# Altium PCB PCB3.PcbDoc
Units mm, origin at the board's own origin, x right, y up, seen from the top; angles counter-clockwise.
Board outline 98.05 x 62.87 mm, 2 copper layers (Top Layer, Bottom Layer); 28 components, 23 nets, 116 pads, 8 vias.
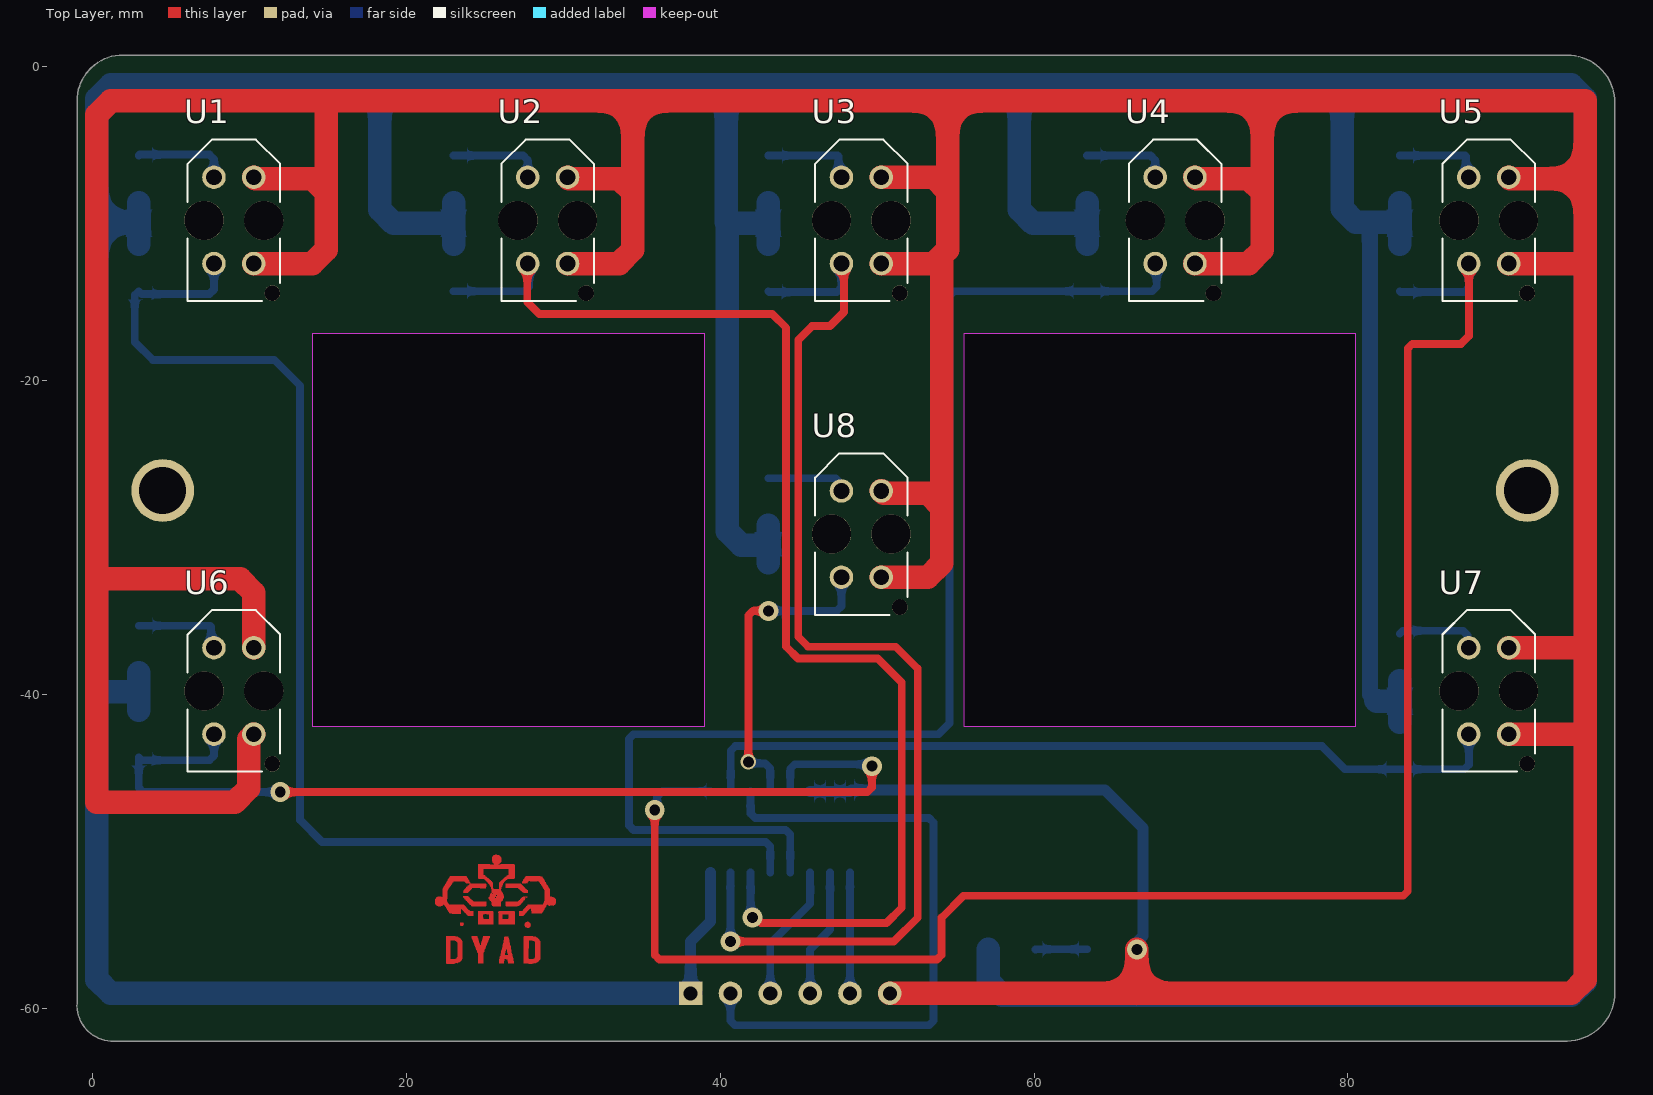
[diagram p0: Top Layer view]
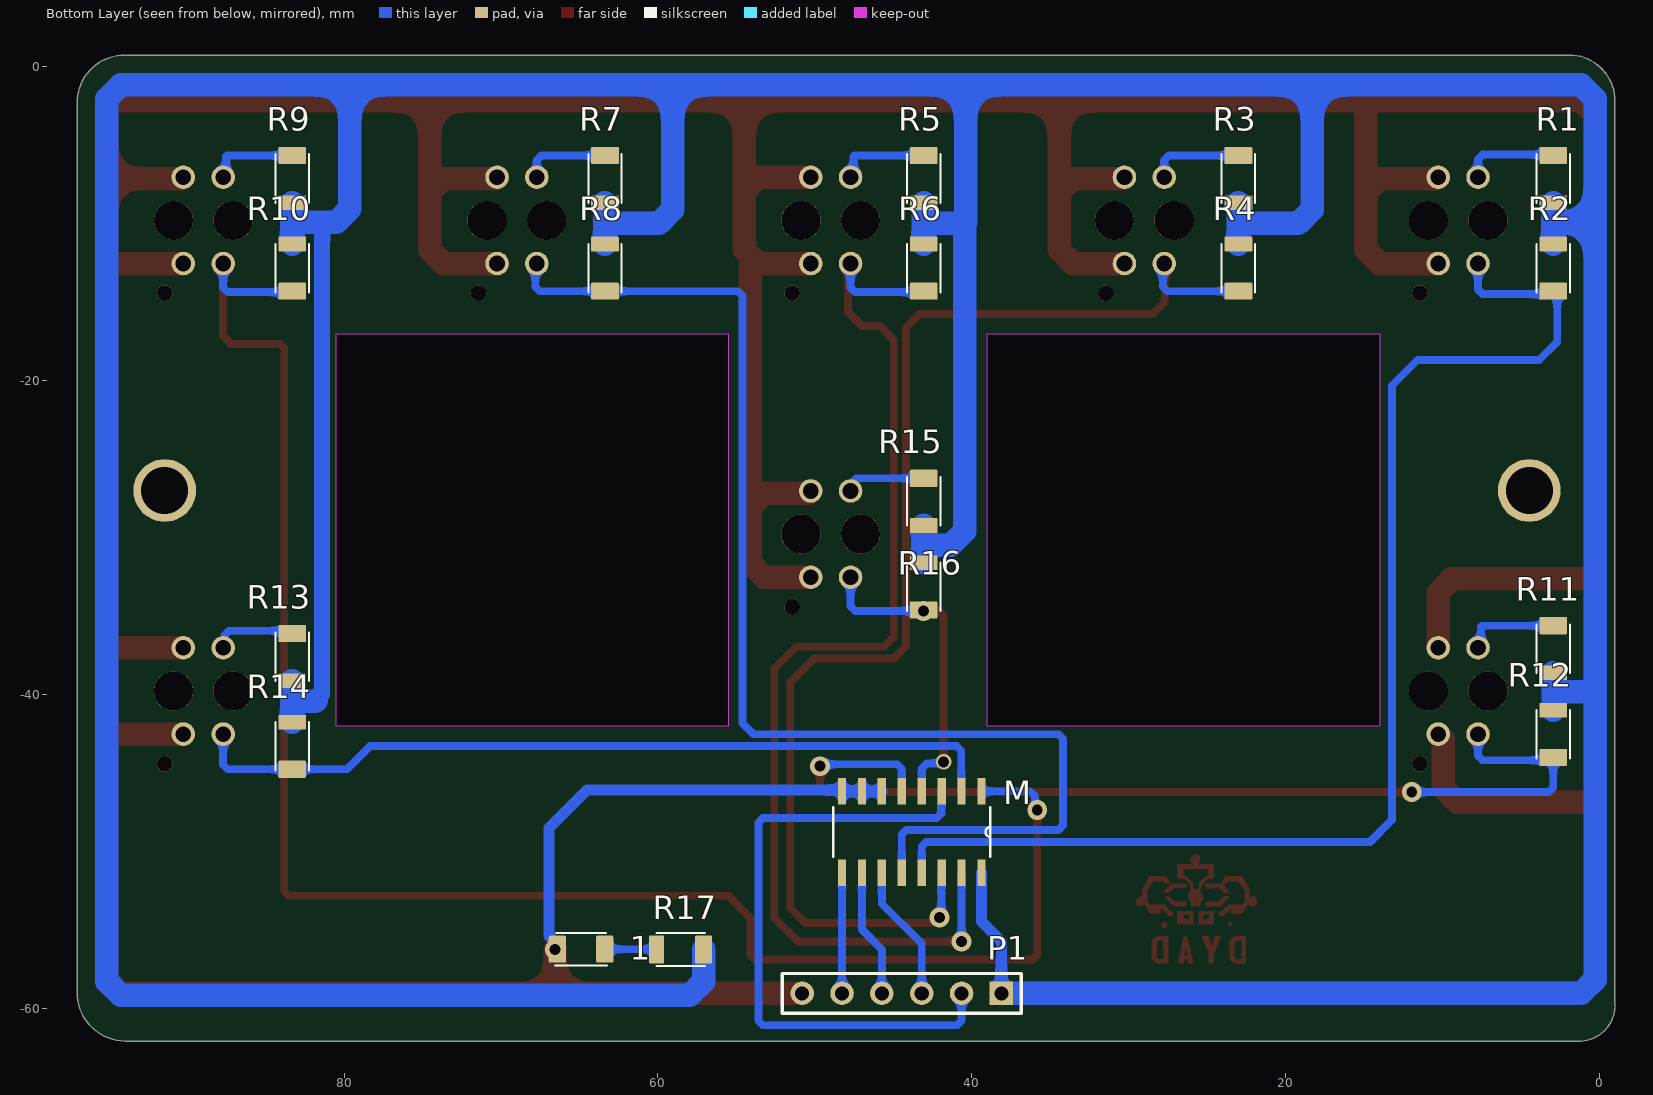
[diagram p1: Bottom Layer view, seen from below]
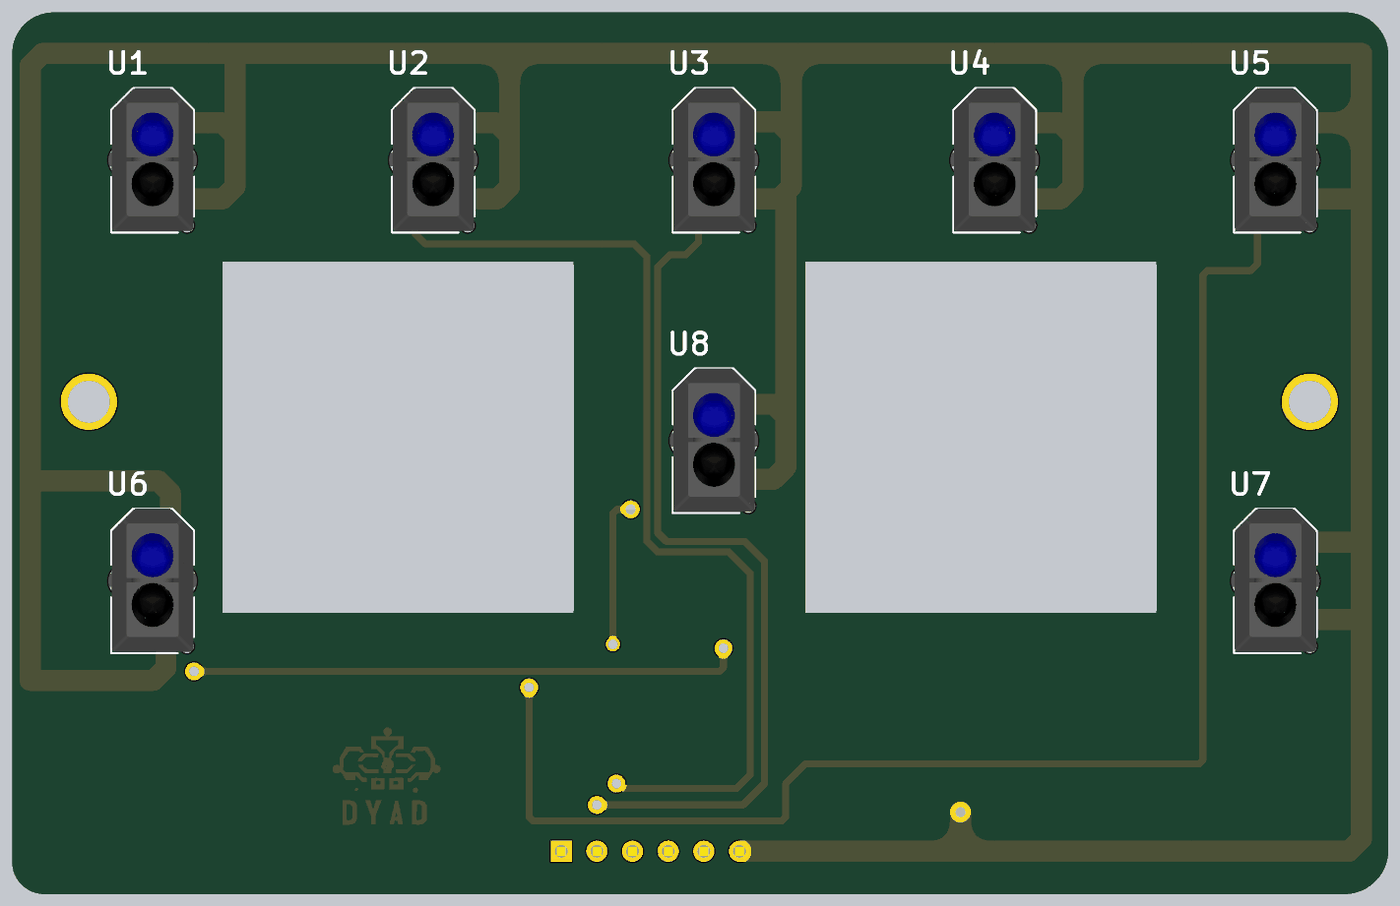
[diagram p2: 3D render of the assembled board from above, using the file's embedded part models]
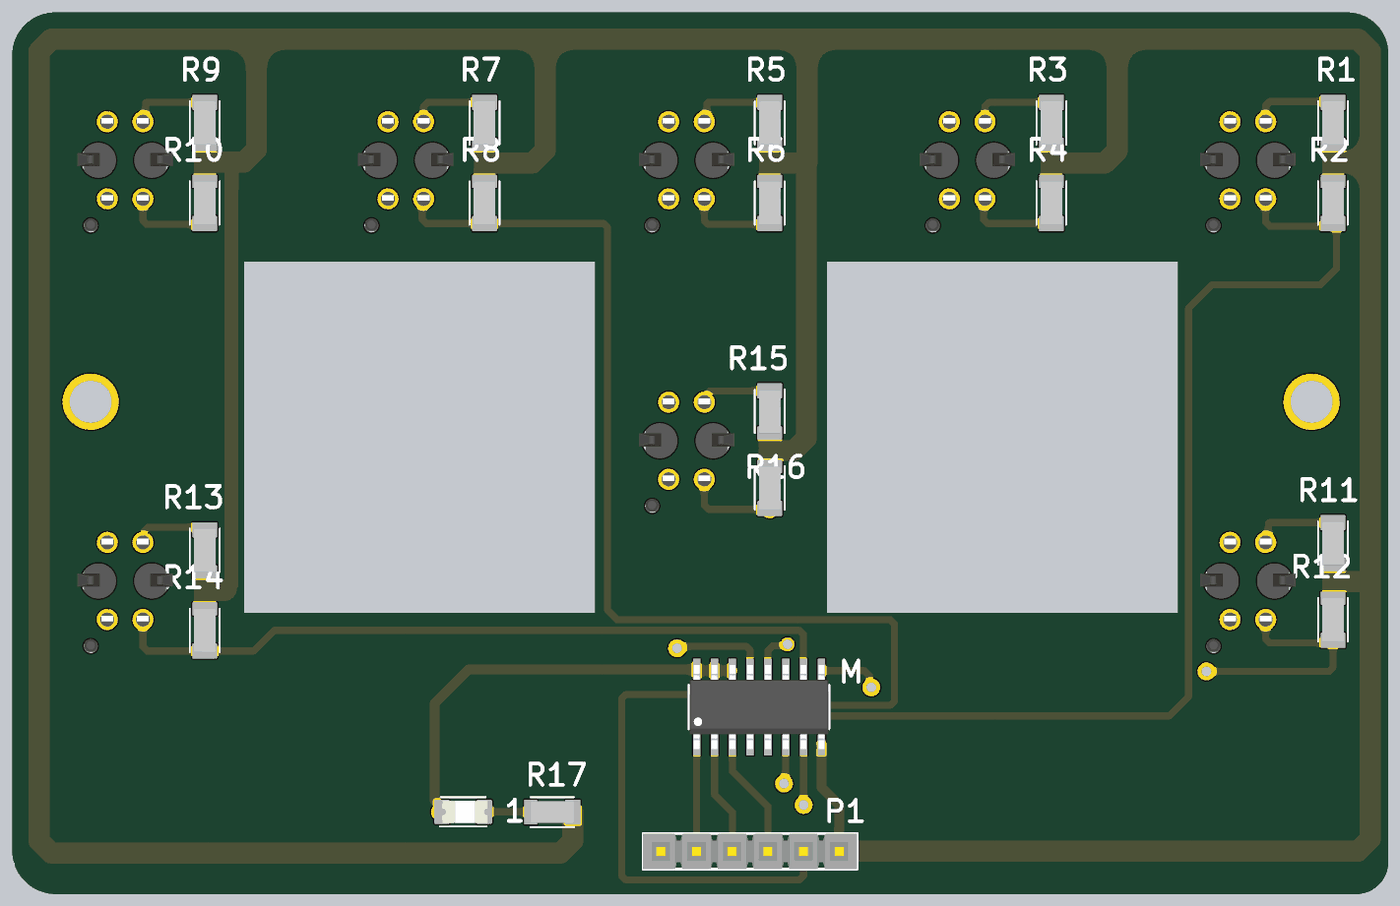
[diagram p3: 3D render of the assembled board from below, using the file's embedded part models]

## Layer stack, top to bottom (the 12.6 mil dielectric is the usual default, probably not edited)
Top Solder: solder mask 0.0102, Solder Resist, Dk 3.5
Top Layer: signal copper 0.0356
Dielectric 1: dielectric 0.32, FR-4, Dk 4.8
Bottom Layer: signal copper 0.0356
Bottom Solder: solder mask 0.0102, Solder Resist, Dk 3.5

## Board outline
1.136,-62.103 cw(c1.27,-59.817) -1.016,-59.686 -1.016,-2.159 cw(c1.905,-2.159) 1.905,0.762 93.98,0.762 cw(c93.98,-2.286) 97.028,-2.286 97.028,-58.928 97.029,-58.991 cw(c93.917,-58.992) 93.983,-62.103 93.98,-62.103
cut-out: 38.989,-42.037 38.989,-17.018 13.97,-17.018 13.97,-42.037
cut-out: 55.499,-42.037 80.518,-42.037 80.518,-17.018 55.499,-17.018

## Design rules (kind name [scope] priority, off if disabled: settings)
Clearance [All] p1: gap=0.254 ignorepadtopadclearanceinfootprint=FALSE except(0: Arc-Hole Track-Hole SMDPad-Hole THPad-Hole Via-Hole Fill-Hole Poly-Hole Region-Hole Text-Hole)
PolygonConnect [All] p1: connectstyle=Relief reliefconductorwidth=0.254 reliefentries=4 polygonreliefangle="90 Angle" airgapwidth=0.254
RoutingVias [All] p1: holewidth=0.711 width=1.27 viastyle="Through Hole" minholewidth=0.711 minwidth=1.27 maxholewidth=0.711 maxwidth=1.27
SolderMaskExpansion [All] p1: expansion=0.102 istentingtop=FALSE
Width [All] p1: maxlimit=2 minlimit=0.5 preferedwidth=1 minimp=50.000000 maximp=50.000000 favimp=50.000000
30 further rules are at their usual default settings.

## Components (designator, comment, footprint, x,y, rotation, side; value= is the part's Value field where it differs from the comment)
1 "LTST-C230KFKT" LEDC3216X110 64.897,-56.241 r180 bottom
M "74HC4051D" SOIC127P600X175-16N 43.815,-48.768 r270 bottom
P1 "Header 6" HDR1X6 38.1,-59.055 r0 bottom
R1 "220" RESC3115X65N 2.921,-7.112 r270 bottom
R2 "2K" RESC3115X65N 2.921,-12.827 r90 bottom
R3 "220" RESC3115X65N 22.987,-7.112 r270 bottom
R4 "2K" RESC3115X65N 22.987,-12.827 r90 bottom
R5 "220" RESC3115X65N 43.053,-7.112 r270 bottom
R6 "2K" RESC3115X65N 43.053,-12.827 r90 bottom
R7 "220" RESC3115X65N 63.373,-7.112 r270 bottom
R8 "2K" RESC3115X65N 63.373,-12.827 r90 bottom
R9 "220" RESC3115X65N 83.312,-7.112 r270 bottom
R10 "2K" RESC3115X65N 83.312,-12.827 r90 bottom
R11 "220" RESC3115X65N 2.921,-37.084 r270 bottom
R12 "2K" RESC3115X65N 2.921,-42.545 r90 bottom
R13 "220" RESC3115X65N 83.312,-37.592 r270 bottom
R14 "2K" RESC3115X65N 83.312,-43.307 r90 bottom
R15 "220" RESC3115X65N 43.053,-27.686 r270 bottom
R16 "2K" RESC3115X65N 43.053,-33.147 r90 bottom
R17 "1879462-3" RESC3115X65N 58.547,-56.261 r0 bottom
U1 "IR_SENSOR" OPTO_TCRT5000 8.984,-9.779 r90 top
U2 "IR_SENSOR" OPTO_TCRT5000 28.984,-9.779 r90 top
U3 "IR_SENSOR" OPTO_TCRT5000 48.984,-9.779 r90 top
U4 "IR_SENSOR" OPTO_TCRT5000 68.984,-9.779 r90 top
U5 "IR_SENSOR" OPTO_TCRT5000 88.984,-9.779 r90 top
U6 "IR_SENSOR" OPTO_TCRT5000 8.984,-39.779 r90 top
U7 "IR_SENSOR" OPTO_TCRT5000 88.984,-39.779 r90 top
U8 "IR_SENSOR" OPTO_TCRT5000 48.984,-29.779 r90 top

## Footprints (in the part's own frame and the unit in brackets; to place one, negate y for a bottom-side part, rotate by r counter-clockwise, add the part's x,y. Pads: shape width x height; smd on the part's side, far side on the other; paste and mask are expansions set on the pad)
HDR1X6 [mm] "Connector; Header; 6 Position"
  rect 1.5x1.5 hole 0.9: 1(0,0)
  round 1.5 hole 0.9: 2(2.54,0) 3(5.08,0) 4(7.62,0) 5(10.16,0) 6(12.7,0)
  silkscreen extent -1.27,-1.27 13.97,1.27, body extent -1.26,-1.25 13.98,1.29, height 8.38
LEDC3216X110 [mm]
  rrect20% 1.1x1.73 smd: A(1.51,0) C(-1.51,0)
  silkscreen extent -1.65,-1.04 1.65,1.04, body extent -1.47,-0.8 1.73,0.8, height 1.13
OPTO_TCRT5000 [mm]
  round 1.5 hole 1: A(2.75,1.27) CATH(2.75,-1.27) COLL(-2.75,1.27) E(-2.75,-1.27)
  round 1 hole 1 unplated: ""(-4.65,-2.45)
  round 2.5 hole 2.5 unplated: ""(0,1.9) ""(0,-1.9)
  silkscreen extent -5.15,-2.95 5.15,2.95, body extent -5.04,-3.4 5.16,3.4, height 7.2
RESC3115X65N [mm]
  rrect14% 1.09x1.77 smd: 1(-1.465,0)
  rrect14% 0.94x1.77 smd: 2(1.54,0)
  silkscreen extent -1.55,-1.06 1.55,1.06, body extent -1.55,-0.77 1.55,0.77, height 0.53
SOIC127P600X175-16N [mil]
  rect 67x21 smd: 1(-102,175) 2(-102,125) 3(-102,75) 4(-102,25) 5(-102,-25) 6(-102,-75) 7(-102,-125) 8(-102,-175) 9(102,-175) 10(102,-125) 11(102,-75) 12(102,-25) 13(102,25) 14(102,75) 15(102,125) 16(102,175)
  silkscreen extent -62,-197 62,197, body extent -118,-195 118,195, height 67

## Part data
1: "Orange 605nm LED Indication - Discrete 2V 1206 (3216 Metric)", Package="1206 Lite-On"
M: "1 Circuit IC Switch 8:1 130Ohm 16-SOIC", Package="SOIC-16 Toshiba"
P1: "Header, 6-Pin"
R1 R2 R3 R4 R5 R6 R7 R8 R9 R10 R11 R12 R13 R14 R15 R16: library part 1879462-3, "RL73H 2B R12 1% 5K RL", Package=None
R17: "RL73H 2B R12 1% 5K RL", Package=None
U1 U2 U3 U4 U5 U6 U7 U8: library part TCRT5000, "950 nm 60 mA Through Hole Reflective Optical Sensor with Transistor Output", Package=None

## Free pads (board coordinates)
  round 4 hole 3: 6(4.445,-27) 6(91.44,-27)

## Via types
v1: diameter 1.27, hole 0.7, Top Layer to Bottom Layer, 7 vias
v2: diameter 1, hole 0.7, Top Layer to Bottom Layer, 1 vias

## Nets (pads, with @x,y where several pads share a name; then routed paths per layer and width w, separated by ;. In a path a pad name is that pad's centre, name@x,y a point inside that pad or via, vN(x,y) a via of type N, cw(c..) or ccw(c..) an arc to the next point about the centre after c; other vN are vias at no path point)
+5: M.16 P1.1 R1.2 R2.2 R3.2 R4.2 R5.2 R6.2 R7.2 R8.2 R9.2 R10.2 R11.2 R12.2 R13.2 R14.2 R15.2 R16.2 R17.1 | length 424.9
  Bottom Layer w0.7: P1.1 38.1,-55.753 39.37,-54.483 M.16
  Bottom Layer w1: 81.407,-9.906 81.407,-40.005 81.788,-40.386
  Bottom Layer w1.5: R12.2 2.921,-39.814 ; R11.2 2.921,-39.814 ; R2.2 2.921,-9.97 ; R1.2 2.921,-9.97 ; R4.2 22.987,-9.97 ; R3.2 22.987,-9.97 ; P1.1 1.133,-59.055 0.254,-58.176 0.254,-39.878 ; 42.873,-30.48 41.328,-30.48 40.45,-29.601 40.45,-9.97 ; R16.2 R15.2 ; R6.2 43.053,-9.97 ; R5.2 43.053,-9.97 ; R17.1 57.082,-58.303 57.961,-59.182 94.244,-59.182 95.123,-58.303 95.123,-2.022 94.244,-1.143 79.629,-1.143 ; R8.2 63.373,-9.97 ; R7.2 63.373,-9.97 ; 81.788,-40.386 81.852,-40.45 83.312,-40.45 ; R14.2 83.312,-40.45 ; R13.2 83.312,-40.45 ; R10.2 83.312,-9.97 ; R9.2 83.312,-9.97 ; 0.254,-39.878 0.254,-9.906 ; 0.254,-39.878 0.318,-39.814 2.921,-39.814 ; 0.254,-9.906 0.254,-2.022 1.133,-1.143 18.288,-1.143 ; 0.254,-9.906 2.857,-9.906 2.921,-9.97 ; 18.288,-1.143 40.386,-1.143 ; 18.288,-1.143 18.288,-9.091 19.167,-9.97 22.987,-9.97 ; 40.386,-1.143 40.386,-9.906 40.45,-9.97 ; 40.386,-1.143 59.055,-1.143 ; 40.45,-9.97 43.053,-9.97 ; 59.055,-1.143 79.629,-1.143 ; 59.055,-1.143 59.055,-9.091 59.934,-9.97 63.373,-9.97 ; 79.629,-1.143 79.629,-9.027 80.508,-9.906 81.407,-9.906 83.248,-9.906 83.312,-9.97
A1: M.3 P1.2 | length 40.9
  Bottom Layer w0.5: P1.2 40.64,-60.794 40.933,-61.087 53.301,-61.087 53.594,-60.794 53.594,-48.172 53.301,-47.879 42.22,-47.879 41.927,-47.586 41.927,-46.194 M.3
D1: M.11 P1.3 | length 8.7
  Bottom Layer w0.5: P1.3 43.18,-55.88 45.72,-53.34 M.11
D2: M.10 P1.4 | length 8.2
  Bottom Layer w0.5: P1.4 45.72,-56.261 46.99,-54.991 M.10
D3: M.9 P1.5 | length 7.7
  Bottom Layer w0.5: P1.5 M.9
GND: 1.C M.6 M.7 M.8 P1.6 U1.CATH U1.E U2.CATH U2.E U3.CATH U3.E U4.CATH U4.E U5.CATH U5.E U6.CATH U6.E U7.CATH U7.E U8.CATH U8.E | length 423.8
  Top Layer w1.5: U6.E 9.93,-42.853 9.93,-45.984 9.051,-46.863 0.254,-46.863 0.254,-32.512 ; U6.CATH 10.254,-33.518 9.375,-32.639 0.381,-32.639 0.254,-32.512 ; U1.E 13.98,-12.529 14.859,-11.65 14.859,-7.991 ; U1.CATH 10.337,-7.112 13.98,-7.112 14.859,-7.991 ; U2.E 33.538,-12.529 34.417,-11.65 34.417,-7.991 ; U2.CATH 30.337,-7.112 33.538,-7.112 34.417,-7.991 ; U8.E 53.223,-32.529 54.102,-31.65 54.102,-28.057 ; U8.CATH 50.403,-27.178 53.223,-27.178 54.102,-28.057 ; U3.E 53.604,-12.529 54.483,-11.65 54.483,-7.908 ; U3.CATH 53.604,-7.029 54.483,-7.908 ; P1.6 66.548,-59.055 ; 54.102,-12.031 54.102,-28.057 ; v1(66.548,-56.261) 66.548,-59.055 ; U4.E 73.67,-12.529 74.549,-11.65 74.549,-7.991 ; U4.CATH 70.337,-7.112 73.67,-7.112 74.549,-7.991 ; U7.E 94.98,-42.529 95.123,-42.672 ; U7.CATH 95.068,-37.029 95.123,-37.084 ; U5.E 95.079,-12.529 95.123,-12.573 ; U5.CATH 90.337,-7.112 95.123,-7.112 ; 0.254,-32.512 0.254,-3.038 1.133,-2.159 14.605,-2.159 ; 14.605,-2.159 34.417,-2.159 ; 14.605,-2.159 14.859,-2.413 14.859,-7.991 ; 34.417,-7.991 34.417,-2.159 ; 34.417,-2.159 54.483,-2.159 ; 54.483,-7.908 54.483,-2.159 ; 54.483,-2.159 74.549,-2.159 ; 66.548,-59.055 94.244,-59.055 95.123,-58.176 95.123,-42.672 ; 74.549,-7.991 74.549,-2.159 ; 74.549,-2.159 95.123,-2.159 95.123,-7.112 ; 95.123,-42.672 95.123,-37.084 ; 95.123,-37.084 95.123,-12.573 ; 95.123,-12.573 95.123,-7.112
  Bottom Layer w0.7: M.6 M.7 M.8 48.343,-46.094 64.509,-46.094 66.929,-48.514 66.929,-55.404 66.548,-55.785 v1(66.548,-56.261) 1.C@66.421,-56.134
Net1_A: 1.A R17.2 | length 3.3
  Bottom Layer w0.5: R17.2 60.107,-56.241 1.A
NetR1_1: R1.1 U1.A | length 6.1
  Bottom Layer w0.5: R1.1 2.98,-5.588 7.421,-5.588 7.714,-5.881 U1.A
NetR3_1: R3.1 U2.A | length 5.9
  Bottom Layer w0.5: R3.1 27.421,-5.647 27.714,-5.94 U2.A
NetR5_1: R5.1 U3.A | length 5.9
  Bottom Layer w0.5: R5.1 47.459,-5.647 47.523,-5.711 47.523,-6.838 U3.A
NetR7_1: R7.1 U4.A | length 5.6
  Bottom Layer w0.5: R7.1 67.421,-5.647 67.714,-5.94 U4.A
NetR9_1: R9.1 U5.A | length 5.6
  Bottom Layer w0.5: R9.1 87.464,-5.647 87.523,-5.706 87.523,-6.838 U5.A
NetR11_1: R11.1 U6.A | length 6.1
  Bottom Layer w0.5: R11.1 7.454,-35.619 7.523,-35.688 7.523,-36.838 U6.A
NetR13_1: R13.1 U7.A | length 5.3
  Bottom Layer w0.5: R13.1 83.498,-35.941 87.337,-35.941 87.63,-36.234 87.63,-36.945 U7.A
NetR15_1: R15.1 U8.A | length 5.2
  Bottom Layer w0.5: R15.1 47.332,-26.221 47.625,-26.514 47.625,-26.94 U8.A
S1: M.13 R2.1 U1.COLL | length 81.7
  Bottom Layer w0.5: U1.COLL 7.714,-14.185 7.421,-14.478 3.107,-14.478 R2.1 2.667,-14.546 2.667,-17.526 3.81,-18.669 11.557,-18.669 13.208,-20.32 13.208,-48.006 14.605,-49.403 42.887,-49.403 43.18,-49.696 M.13
S2: M.14 R4.1 U2.COLL | length 82.1
  Top Layer w0.5: U2.COLL 27.686,-12.557 27.686,-14.986 28.448,-15.748 43.307,-15.748 44.192,-16.633 44.192,-36.953 44.95,-37.711 50.03,-37.711 51.562,-39.243 51.562,-53.594 50.59,-54.566 42.583,-54.566 42.245,-54.229 v1(42.037,-54.229)
  Bottom Layer w0.5: R4.1 27.52,-14.292 27.813,-13.999 27.813,-12.628 U2.COLL ; M.14 41.927,-51.376 41.927,-54.119 v1(42.037,-54.229)
S3: M.15 R6.1 U3.COLL | length 73.4
  Top Layer w0.5: v1(40.64,-55.753) 51.054,-55.753 52.578,-54.229 52.578,-38.354 51.181,-36.957 45.593,-36.957 44.958,-36.322 44.958,-17.399 45.847,-16.51 46.99,-16.51 47.879,-15.621 47.879,-12.694 U3.COLL
  Bottom Layer w0.5: v1(40.64,-55.753) M.15 ; R6.1 43.112,-14.351 47.421,-14.351 47.714,-14.058 U3.COLL
S4: M.12 R8.1 U4.COLL | length 81.5
  Bottom Layer w0.5: M.12 44.45,-48.934 44.157,-48.641 34.464,-48.641 34.171,-48.348 34.171,-42.834 34.464,-42.541 53.909,-42.541 54.61,-41.84 54.61,-14.585 54.903,-14.292 R8.1 67.525,-14.292 67.818,-13.999 67.818,-12.633 U4.COLL
S5: M.1 R10.1 U5.COLL | length 114.5
  Top Layer w0.5: v1(35.814,-47.367) 35.814,-56.603 36.107,-56.896 53.809,-56.896 54.102,-56.603 54.102,-54.229 55.499,-52.832 83.527,-52.832 83.82,-52.539 83.82,-17.946 84.113,-17.653 87.21,-17.653 87.714,-17.149 U5.COLL
  Bottom Layer w0.5: v1(35.814,-47.367) 35.961,-47.22 35.961,-46.508 36.292,-46.177 M.1 ; R10.1 83.371,-14.351 87.421,-14.351 87.714,-14.058 U5.COLL
S6: M.5 R12.1 U6.COLL | length 63.4
  Top Layer w0.5: v1(11.938,-46.228) 49.364,-46.228 49.657,-45.935 v1(49.657,-44.577)
  Bottom Layer w0.5: U6.COLL 7.714,-43.903 7.421,-44.196 3.107,-44.196 R12.1 2.921,-45.935 3.214,-46.228 v1(11.938,-46.228) ; M.5 44.45,-44.743 44.743,-44.45 49.53,-44.45 v1(49.657,-44.577)
S7: M.2 R14.1 U7.COLL | length 52.5
  Bottom Layer w0.5: M.2 40.657,-46.16 40.657,-43.588 40.95,-43.295 78.347,-43.295 79.824,-44.772 R14.1 87.421,-44.772 87.714,-44.479 U7.COLL
S8: M.4 R16.1 U8.COLL | length 20.4
  Top Layer w0.5: v2(41.783,-44.299) 41.783,-34.964 42.076,-34.671 v1(43.053,-34.671)
  Bottom Layer w0.5: v2(41.783,-44.299) 41.879,-44.395 42.848,-44.395 43.18,-44.727 M.4 ; v1(43.053,-34.671) 47.421,-34.671 47.714,-34.378 U8.COLL
pads on no net: U1. U2. U3. U4. U5. U6. U7. U8.

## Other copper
Top Layer:
  region: 25.303,-52.703 25.322,-52.703 25.322,-52.723 25.303,-52.723
  region: 25.342,-52.703 25.361,-52.703 25.361,-52.742 25.342,-52.742 25.342,-52.723
  region: 23.091,-55.439 23.188,-55.439 23.188,-55.458 23.246,-55.458 23.246,-55.478 23.285,-55.478 23.285,-55.497 23.324,-55.497 23.324,-55.517 23.343,-55.517 23.343,-55.536 23.363,-55.536 23.363,-55.555 23.402,-55.555 23.402,-55.575 23.421,-55.575 23.421,-55.594 23.44,-55.594 23.44,-55.614 23.46,-55.614 23.46,-55.652 23.479,-55.652 23.479,-55.672 23.499,-55.672 23.499,-55.711 23.518,-55.711 23.518,-55.749 23.537,-55.749 23.537,-55.788 23.557,-55.788 23.557,-56.797 23.537,-56.797 23.537,-56.836 23.518,-56.836 23.518,-56.894 23.499,-56.894 23.499,-56.933 23.479,-56.933 23.479,-56.952 23.46,-56.952 23.46,-56.972 23.44,-56.972 23.44,-56.991 23.421,-56.991 23.421,-57.011 23.402,-57.011 23.402,-57.03 23.382,-57.03 23.382,-57.049 23.343,-57.049 23.343,-57.069 23.304,-57.069 23.304,-57.088 23.266,-57.088 23.266,-57.108 23.207,-57.108 23.207,-57.127 23.11,-57.127 23.11,-57.146 23.033,-57.146 23.033,-57.166 22.548,-57.166 22.548,-57.146 22.509,-57.146 22.509,-55.42 23.091,-55.42 hole: 23.052,-55.711 22.819,-55.711 22.819,-56.836 22.839,-56.836 22.839,-56.855 23.013,-56.855 23.013,-56.836 23.11,-56.836 23.11,-56.817 23.149,-56.817 23.149,-56.797 23.169,-56.797 23.169,-56.758 23.188,-56.758 23.188,-56.72 23.207,-56.72 23.207,-55.846 23.188,-55.846 23.188,-55.808 23.169,-55.808 23.169,-55.769 23.13,-55.769 23.13,-55.749 23.11,-55.749 23.11,-55.73 23.052,-55.73
  region: 23.421,-54.702 23.402,-54.702 23.402,-54.605 23.421,-54.605 23.421,-54.566 23.44,-54.566 23.44,-54.546 23.576,-54.546 23.576,-54.566 23.615,-54.566 23.615,-54.624 23.634,-54.624 23.634,-54.644 23.615,-54.644 23.615,-54.702 23.596,-54.702 23.596,-54.721 23.576,-54.721 23.576,-54.741 23.557,-54.741 23.557,-54.76 23.479,-54.76 23.479,-54.741 23.44,-54.741 23.44,-54.721 23.421,-54.721
  region: 27.787,-54.857 27.767,-54.857 27.767,-54.876 27.67,-54.876 27.67,-54.857 27.612,-54.857 27.612,-54.838 27.593,-54.838 27.593,-54.818 27.573,-54.818 27.573,-54.799 27.554,-54.799 27.554,-54.741 27.534,-54.741 27.534,-54.605 27.554,-54.605 27.554,-54.566 27.573,-54.566 27.573,-54.546 27.612,-54.546 27.612,-54.527 27.67,-54.527 27.67,-54.508 27.748,-54.508 27.748,-54.527 27.787,-54.527 27.787,-54.546 27.845,-54.546 27.845,-54.585 27.864,-54.585 27.864,-54.605 27.884,-54.605 27.884,-54.682 27.903,-54.682 27.903,-54.721 27.884,-54.721 27.884,-54.799 27.864,-54.799 27.864,-54.818 27.845,-54.818 27.845,-54.838 27.825,-54.838 27.825,-54.857 27.806,-54.857
  region: 26.758,-53.829 26.855,-53.829 26.855,-53.848 26.875,-53.848 26.875,-54.644 25.866,-54.644 25.866,-54.139 25.866,-54.12 25.866,-53.906 25.846,-53.906 25.846,-53.887 25.866,-53.887 25.866,-53.829 26.215,-53.829 26.215,-53.809 26.758,-53.809 hole: 26.448,-54.042 26.118,-54.042 26.118,-54.275 26.137,-54.275 26.137,-54.294 26.448,-54.294 26.448,-54.275 26.487,-54.275 26.487,-54.12 26.467,-54.12 26.467,-54.061 26.448,-54.061
  region: 24.779,-53.499 24.139,-53.499 24.139,-53.479 24.119,-53.479 24.119,-53.441 24.1,-53.441 24.1,-53.421 24.081,-53.421 24.081,-53.402 24.061,-53.402 24.061,-53.382 24.042,-53.382 24.042,-53.363 24.003,-53.363 24.003,-53.324 23.984,-53.324 23.984,-53.305 23.964,-53.305 23.964,-53.285 23.945,-53.285 23.945,-53.266 23.925,-53.266 23.925,-53.247 23.906,-53.247 23.906,-53.227 23.887,-53.227 23.887,-53.208 23.867,-53.208 23.867,-53.188 23.848,-53.188 23.848,-53.169 23.828,-53.169 23.828,-53.149 23.809,-53.149 23.809,-53.13 23.79,-53.13 23.79,-53.111 23.77,-53.111 23.77,-53.091 23.751,-53.091 23.751,-53.052 23.712,-53.052 23.712,-53.014 23.693,-53.014 23.693,-52.994 23.673,-52.994 23.673,-52.975 23.654,-52.975 23.654,-52.955 23.634,-52.955 23.634,-52.917 23.615,-52.917 23.615,-52.878 23.906,-52.878 23.906,-52.897 23.945,-52.897 23.945,-52.936 23.984,-52.936 23.984,-52.955 24.003,-52.955 24.003,-52.994 24.022,-52.994 24.022,-53.014 24.042,-53.014 24.042,-53.033 24.061,-53.033 24.061,-53.052 24.081,-53.052 24.081,-53.072 24.1,-53.072 24.1,-53.091 24.119,-53.091 24.119,-53.111 24.158,-53.111 24.158,-53.13 24.178,-53.13 24.178,-53.149 24.197,-53.149 24.197,-53.169 24.216,-53.169 24.216,-53.188 24.236,-53.188 24.236,-53.208 25.051,-53.208 25.051,-53.227 25.07,-53.227 25.07,-53.479 25.051,-53.479 25.051,-53.499 24.799,-53.499
  region: 27.185,-52.082 27.282,-52.082 27.282,-52.102 27.301,-52.102 27.301,-52.121 27.321,-52.121 27.321,-52.141 27.34,-52.141 27.34,-52.16 27.36,-52.16 27.36,-52.179 27.379,-52.179 27.379,-52.199 27.398,-52.199 27.398,-52.218 27.418,-52.218 27.418,-52.238 27.437,-52.238 27.437,-52.276 27.476,-52.276 27.476,-52.296 27.495,-52.296 27.495,-52.315 27.515,-52.315 27.515,-52.335 27.534,-52.335 27.534,-52.354 27.554,-52.354 27.554,-52.373 27.573,-52.373 27.573,-52.412 27.612,-52.412 27.612,-52.432 27.631,-52.432 27.631,-52.451 27.651,-52.451 27.651,-52.47 27.67,-52.47 27.67,-52.49 27.709,-52.49 27.709,-52.509 27.728,-52.509 27.728,-52.626 27.709,-52.626 27.709,-52.645 27.476,-52.645 27.476,-52.626 27.437,-52.626 27.437,-52.606 27.398,-52.606 27.398,-52.587 27.379,-52.587 27.379,-52.567 27.36,-52.567 27.36,-52.548 27.34,-52.548 27.34,-52.529 27.321,-52.529 27.321,-52.509 27.301,-52.509 27.301,-52.49 27.282,-52.49 27.282,-52.47 27.243,-52.47 27.243,-52.451 27.224,-52.451 27.224,-52.432 27.204,-52.432 27.204,-52.412 27.185,-52.412 27.185,-52.393 27.166,-52.393 27.166,-52.373 27.146,-52.373 27.146,-52.354 27.127,-52.354 27.127,-52.335 26.312,-52.335 26.312,-52.082 27.166,-52.082
  region: 24.934,-53.829 25.478,-53.829 25.478,-53.848 25.516,-53.848 25.516,-54.023 25.516,-54.042 25.516,-54.644 24.566,-54.644 24.566,-53.829 24.837,-53.829 24.837,-53.809 24.857,-53.809 24.857,-53.829 24.896,-53.829 24.896,-53.809 24.934,-53.809 hole: 25.07,-54.023 24.973,-54.023 24.973,-54.042 24.915,-54.042 24.915,-54.061 24.896,-54.061 24.896,-54.217 24.915,-54.217 24.915,-54.294 25.225,-54.294 25.225,-54.042 25.07,-54.042
  region: 26.467,-55.458 26.487,-55.458 26.487,-55.555 26.506,-55.555 26.506,-55.652 26.525,-55.652 26.525,-55.749 26.545,-55.749 26.545,-55.846 26.564,-55.846 26.564,-55.924 26.584,-55.924 26.584,-55.982 26.603,-55.982 26.603,-56.041 26.603,-56.06 26.622,-56.06 26.622,-56.176 26.642,-56.176 26.642,-56.293 26.661,-56.293 26.661,-56.39 26.681,-56.39 26.681,-56.487 26.7,-56.487 26.7,-56.564 26.719,-56.564 26.719,-56.623 26.739,-56.623 26.739,-56.72 26.758,-56.72 26.758,-56.817 26.778,-56.817 26.778,-56.914 26.797,-56.914 26.797,-57.011 26.816,-57.011 26.816,-57.146 26.506,-57.146 26.506,-57.127 26.487,-57.127 26.487,-57.049 26.467,-57.049 26.467,-57.011 26.448,-57.011 26.448,-56.894 26.428,-56.894 26.428,-56.875 26.351,-56.875 26.351,-56.855 26.234,-56.855 26.234,-56.875 26.215,-56.875 26.215,-56.972 26.196,-56.972 26.196,-57.069 26.176,-57.069 26.176,-57.127 26.157,-57.127 26.157,-57.146 25.904,-57.146 25.904,-57.127 25.885,-57.127 25.885,-56.991 25.904,-56.991 25.904,-56.894 25.924,-56.894 25.924,-56.817 25.943,-56.817 25.943,-56.739 25.963,-56.739 25.963,-56.7 25.982,-56.7 25.982,-56.623 26.001,-56.623 26.001,-56.526 26.021,-56.526 26.021,-56.429 26.04,-56.429 26.04,-56.351 26.06,-56.351 26.06,-56.273 26.079,-56.273 26.079,-56.215 26.098,-56.215 26.098,-56.138 26.118,-56.138 26.118,-56.041 26.137,-56.041 26.137,-55.963 26.157,-55.963 26.157,-55.866 26.176,-55.866 26.176,-55.769 26.196,-55.769 26.196,-55.672 26.215,-55.672 26.215,-55.614 26.234,-55.614 26.234,-55.478 26.254,-55.478 26.254,-55.439 26.467,-55.439 hole: 26.37,-56.293 26.351,-56.293 26.351,-56.332 26.331,-56.332 26.331,-56.37 26.312,-56.37 26.312,-56.429 26.312,-56.448 26.312,-56.506 26.293,-56.506 26.293,-56.603 26.37,-56.603 26.37,-56.584 26.428,-56.584 26.428,-56.564 26.409,-56.564 26.409,-56.467 26.39,-56.467 26.39,-56.39 26.37,-56.39
  region: 27.67,-52.917 27.651,-52.917 27.651,-52.936 27.631,-52.936 27.631,-52.955 27.612,-52.955 27.612,-52.975 27.573,-52.975 27.573,-52.994 27.534,-52.994 27.534,-53.014 27.515,-53.014 27.515,-52.994 27.495,-52.994 27.495,-53.014 27.515,-53.014 27.515,-53.033 27.534,-53.033 27.534,-53.052 27.515,-53.052 27.515,-53.091 27.495,-53.091 27.495,-53.111 27.476,-53.111 27.476,-53.13 27.437,-53.13 27.437,-53.169 27.418,-53.169 27.418,-53.188 27.398,-53.188 27.398,-53.208 27.379,-53.208 27.379,-53.227 27.36,-53.227 27.36,-53.266 27.34,-53.266 27.34,-53.285 27.321,-53.285 27.321,-53.305 27.301,-53.305 27.301,-53.324 27.282,-53.324 27.282,-53.344 27.263,-53.344 27.263,-53.363 27.243,-53.363 27.243,-53.382 27.224,-53.382 27.224,-53.402 27.204,-53.402 27.204,-53.421 27.185,-53.421 27.185,-53.441 27.166,-53.441 27.166,-53.46 27.146,-53.46 27.146,-53.479 27.049,-53.479 27.049,-53.499 26.351,-53.499 26.351,-53.479 26.331,-53.479 26.331,-53.46 26.312,-53.46 26.312,-53.208 27.127,-53.208 27.127,-53.188 27.146,-53.188 27.146,-53.169 27.166,-53.169 27.166,-53.149 27.185,-53.149 27.185,-53.13 27.204,-53.13 27.204,-53.111 27.224,-53.111 27.224,-53.091 27.243,-53.091 27.243,-53.072 27.263,-53.072 27.263,-53.052 27.282,-53.052 27.282,-53.014 27.301,-53.014 27.301,-52.994 27.321,-52.994 27.321,-52.975 27.34,-52.975 27.34,-52.955 27.36,-52.955 27.36,-52.936 27.379,-52.936 27.379,-52.917 27.418,-52.917 27.418,-52.936 27.437,-52.936 27.437,-52.897 27.67,-52.897 hole: 27.515,-52.917 27.495,-52.917 27.495,-52.936 27.515,-52.936 hole: 27.612,-52.917 27.593,-52.917 27.593,-52.936 27.612,-52.936 hole: 27.573,-52.936 27.554,-52.936 27.554,-52.955 27.573,-52.955
  region: 24.76,-55.885 24.76,-55.846 24.779,-55.846 24.779,-55.808 24.799,-55.808 24.799,-55.73 24.818,-55.73 24.818,-55.652 24.837,-55.652 24.837,-55.594 24.857,-55.594 24.857,-55.517 24.876,-55.517 24.876,-55.439 24.896,-55.439 24.896,-55.42 25.303,-55.42 25.303,-55.478 25.284,-55.478 25.284,-55.497 25.264,-55.497 25.264,-55.555 25.245,-55.555 25.245,-55.594 25.225,-55.594 25.225,-55.633 25.206,-55.633 25.206,-55.672 25.187,-55.672 25.187,-55.73 25.167,-55.73 25.167,-55.788 25.148,-55.788 25.148,-55.808 25.128,-55.808 25.128,-55.866 25.109,-55.866 25.109,-55.924 25.09,-55.924 25.09,-55.963 25.07,-55.963 25.07,-56.021 25.051,-56.021 25.051,-56.079 25.031,-56.079 25.031,-56.118 25.012,-56.118 25.012,-56.157 24.993,-56.157 24.993,-56.215 24.973,-56.215 24.973,-56.254 24.954,-56.254 24.954,-56.312 24.934,-56.312 24.934,-56.39 24.915,-56.39 24.915,-56.448 24.896,-56.448 24.896,-56.467 24.876,-56.467 24.876,-57.146 24.566,-57.146 24.566,-57.127 24.546,-57.127 24.546,-56.467 24.527,-56.467 24.527,-56.429 24.507,-56.429 24.507,-56.351 24.488,-56.351 24.488,-56.312 24.469,-56.312 24.469,-56.273 24.449,-56.273 24.449,-56.235 24.43,-56.235 24.43,-56.176 24.41,-56.176 24.41,-56.118 24.391,-56.118 24.391,-56.079 24.372,-56.079 24.372,-56.021 24.352,-56.021 24.352,-55.963 24.333,-55.963 24.333,-55.924 24.313,-55.924 24.313,-55.885 24.294,-55.885 24.294,-55.827 24.275,-55.827 24.275,-55.769 24.255,-55.769 24.255,-55.73 24.236,-55.73 24.236,-55.672 24.216,-55.672 24.216,-55.652 24.197,-55.652 24.197,-55.594 24.178,-55.594 24.178,-55.555 24.158,-55.555 24.158,-55.497 24.139,-55.497 24.139,-55.458 24.119,-55.458 24.119,-55.439 24.139,-55.439 24.139,-55.42 24.488,-55.42 24.488,-55.458 24.507,-55.458 24.507,-55.517 24.527,-55.517 24.527,-55.575 24.546,-55.575 24.546,-55.652 24.566,-55.652 24.566,-55.711 24.585,-55.711 24.585,-55.769 24.604,-55.769 24.604,-55.846 24.624,-55.846 24.624,-55.905 24.643,-55.905 24.643,-55.963 24.663,-55.963 24.663,-56.002 24.682,-56.002 24.682,-56.099 24.701,-56.099 24.701,-56.06 24.721,-56.06 24.721,-55.982 24.74,-55.982 24.74,-55.924 24.76,-55.924 24.76,-55.905
  region: 325 vertices and 0 holes, not listed, extent 21.81,-54.12 24.236,-51.597
  region: 24.43,-52.335 24.158,-52.335 24.158,-52.373 24.139,-52.373 24.139,-52.393 24.119,-52.393 24.119,-52.412 24.1,-52.412 24.1,-52.432 24.081,-52.432 24.081,-52.451 24.061,-52.451 24.061,-52.47 24.042,-52.47 24.042,-52.49 24.022,-52.49 24.022,-52.509 24.003,-52.509 24.003,-52.529 23.984,-52.529 23.984,-52.548 23.964,-52.548 23.964,-52.567 23.945,-52.567 23.945,-52.587 23.925,-52.587 23.925,-52.606 23.906,-52.606 23.906,-52.626 23.887,-52.626 23.887,-52.645 23.634,-52.645 23.634,-52.606 23.615,-52.606 23.615,-52.567 23.634,-52.567 23.634,-52.47 23.673,-52.47 23.673,-52.451 23.693,-52.451 23.693,-52.432 23.712,-52.432 23.712,-52.412 23.731,-52.412 23.731,-52.393 23.751,-52.393 23.751,-52.373 23.77,-52.373 23.77,-52.354 23.79,-52.354 23.79,-52.335 23.809,-52.335 23.809,-52.296 23.828,-52.296 23.828,-52.276 23.867,-52.276 23.867,-52.257 23.887,-52.257 23.887,-52.218 23.906,-52.218 23.906,-52.199 23.945,-52.199 23.945,-52.179 23.964,-52.179 23.964,-52.16 23.984,-52.16 23.984,-52.141 24.003,-52.141 24.003,-52.121 24.022,-52.121 24.022,-52.082 25.051,-52.082 25.051,-52.102 25.07,-52.102 25.07,-52.257 25.051,-52.257 25.051,-52.335 25.031,-52.335 25.031,-52.354 24.701,-52.354 24.701,-52.335 24.449,-52.335
  region: 28.039,-55.439 28.136,-55.439 28.136,-55.458 28.213,-55.458 28.213,-55.478 28.252,-55.478 28.252,-55.497 28.291,-55.497 28.291,-55.517 28.31,-55.517 28.31,-55.536 28.349,-55.536 28.349,-55.555 28.369,-55.555 28.369,-55.575 28.388,-55.575 28.388,-55.594 28.407,-55.594 28.407,-55.614 28.427,-55.614 28.427,-55.652 28.446,-55.652 28.446,-55.672 28.466,-55.672 28.466,-55.691 28.485,-55.691 28.485,-55.749 28.504,-55.749 28.504,-55.846 28.524,-55.846 28.524,-56.797 28.504,-56.797 28.504,-56.875 28.485,-56.875 28.485,-56.914 28.466,-56.914 28.466,-56.933 28.446,-56.933 28.446,-56.952 28.427,-56.952 28.427,-56.991 28.407,-56.991 28.407,-57.011 28.369,-57.011 28.369,-57.03 28.349,-57.03 28.349,-57.049 28.31,-57.049 28.31,-57.069 28.291,-57.069 28.291,-57.088 28.252,-57.088 28.252,-57.108 28.194,-57.108 28.194,-57.127 28.116,-57.127 28.116,-57.146 28,-57.146 28,-57.166 27.787,-57.166 27.787,-57.146 27.495,-57.146 27.495,-57.127 27.476,-57.127 27.476,-55.439 27.495,-55.439 27.495,-55.42 28.039,-55.42 hole: 28.019,-55.711 27.806,-55.711 27.806,-56.215 27.787,-56.215 27.787,-56.681 27.787,-56.7 27.787,-56.817 27.806,-56.817 27.806,-56.855 27.922,-56.855 27.922,-56.836 28.058,-56.836 28.058,-56.817 28.116,-56.817 28.116,-56.797 28.136,-56.797 28.136,-56.758 28.155,-56.758 28.155,-56.7 28.175,-56.7 28.175,-55.846 28.155,-55.846 28.155,-55.808 28.136,-55.808 28.136,-55.769 28.116,-55.769 28.116,-55.749 28.078,-55.749 28.078,-55.73 28.019,-55.73
  region: 335 vertices and 0 holes, not listed, extent 27.166,-54.12 29.513,-51.597
  region: 275 vertices and 5 holes, not listed, extent 24.566,-53.499 26.875,-50.22

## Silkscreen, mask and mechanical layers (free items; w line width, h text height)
Mechanical 1:
  lines w0.254: -0.889,-59.753 -0.889,-2.159 cw(c1.905,-2.159) 1.905,0.635 93.98,0.635 cw(c93.98,-2.286) 96.901,-2.286 96.901,-58.928 cw(c93.916,-58.991) 93.98,-61.976 1.206,-61.976 ; -0.889,-59.69 ccw(c1.27,-59.817) 1.143,-61.976 ; 38.946,-41.994 38.946,-16.994 ; 38.981,-41.994 13.946,-41.994 13.946,-16.994 38.981,-16.994 ; 55.471,-41.994 55.471,-16.994 80.471,-16.994 80.471,-41.994 55.471,-41.994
